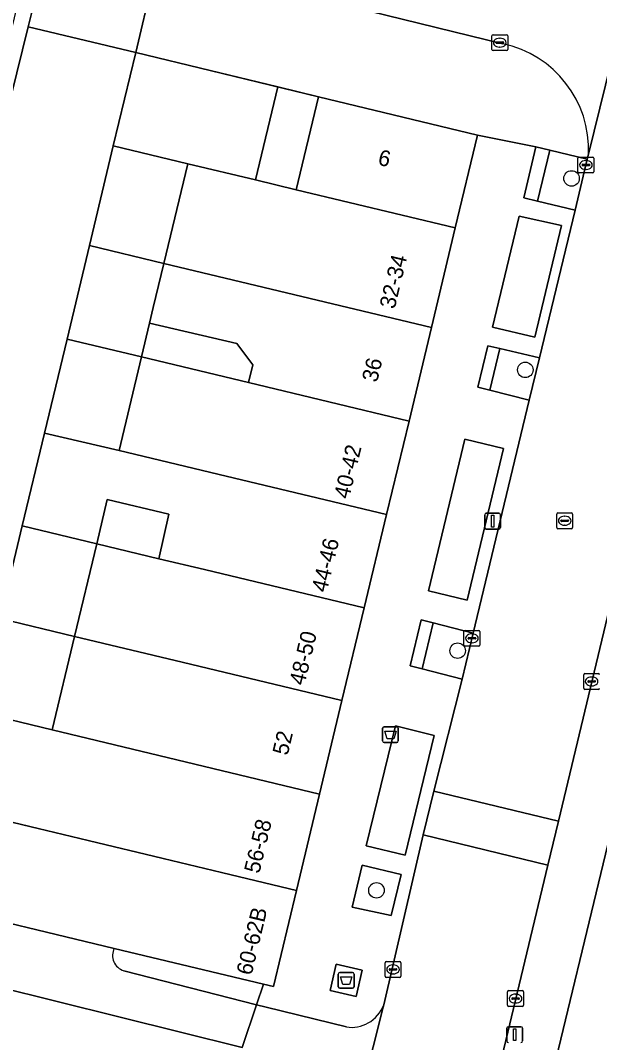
# Model space of a CAD drawing. Extents: x 162803 to 163818, y 381639 to 382475.
# Drawn here: x 163131.9 to 163168.5, y 382070.7 to 382135.2 of the extents above; entities that cross this region are included whole.
import ezdxf

# ---------------------------------------------------------------- set-up
doc = ezdxf.new("R2010")
doc.units = 0
for name, color, linetype in [('IMGEO_Afval_apart_plaats', 7, 'Continuous'), ('IMGEO_Afvalbak', 7, 'Continuous'), ('IMGEO_Boom', 7, 'Continuous'), ('IMGEO_Erf', 7, 'Continuous'), ('IMGEO_Groenvoorziening', 7, 'Continuous'), ('IMGEO_Kolk', 7, 'Continuous'), ('IMGEO_Lichtmast', 7, 'Continuous'), ('IMGEO_Muur', 7, 'Continuous'), ('IMGEO_Pand', 7, 'Continuous'), ('IMGEO_Pand_nummerreeks', 7, 'Continuous'), ('IMGEO_Rijbaan_lokaal_open', 7, 'Continuous'), ('IMGEO_Rioolput', 7, 'Continuous'), ('IMGEO_Voetpad_gesloten', 7, 'Continuous'), ('IMGEO_Voetpad_open', 7, 'Continuous')]:
    doc.layers.add(name, color=color, linetype=linetype)

msp = doc.modelspace()

# ---------------------------------------------------------------- linework, layer by layer
at = {"layer": 'IMGEO_Afval_apart_plaats'}
for p, q in [((163152.072, 382075.169), (163152.862, 382075.169)), ((163152.862, 382075.169), (163152.072, 382075.169)), ((163151.972, 382074.269), (163151.972, 382075.069)), ((163151.972, 382075.069), (163151.972, 382074.269)), ((163152.962, 382075.069), (163152.962, 382074.269)), ((163152.962, 382074.269), (163152.962, 382075.069)), ((163152.862, 382074.169), (163152.072, 382074.169)), ((163152.072, 382074.169), (163152.862, 382074.169))]:
    msp.add_line(p, q, dxfattribs=at)
msp.add_lwpolyline([(163152.115, 382074.883), (163152.819, 382074.883), (163152.67, 382074.413), (163152.264, 382074.413), (163152.115, 382074.883)], dxfattribs=at)
for centre, start, end in [((163152.072, 382075.069), 90, 180), ((163152.072, 382075.069), 90, 180), ((163152.862, 382075.069), 0, 90), ((163152.862, 382075.069), 360, 90), ((163152.072, 382074.269), 180, 270), ((163152.072, 382074.269), 180, 270), ((163152.862, 382074.269), 270, 0), ((163152.862, 382074.269), 270, 0)]:
    msp.add_arc(centre, 0.1, start, end, dxfattribs=at)
at = {"layer": 'IMGEO_Afvalbak'}
for p, q in [((163154.766, 382089.765), (163154.766, 382090.565)), ((163154.766, 382090.565), (163154.766, 382089.765)), ((163154.866, 382090.665), (163155.656, 382090.665)), ((163155.656, 382090.665), (163154.866, 382090.665)), ((163155.756, 382090.565), (163155.756, 382089.765)), ((163155.756, 382089.765), (163155.756, 382090.565)), ((163155.656, 382089.665), (163154.866, 382089.665)), ((163154.866, 382089.665), (163155.656, 382089.665))]:
    msp.add_line(p, q, dxfattribs=at)
msp.add_lwpolyline([(163154.909, 382090.379), (163155.613, 382090.379), (163155.464, 382089.909), (163155.058, 382089.909), (163154.909, 382090.379)], dxfattribs=at)
for centre, start, end in [((163154.866, 382090.565), 90, 180), ((163154.866, 382090.565), 90, 180), ((163155.656, 382090.565), 0, 90), ((163155.656, 382090.565), 360, 90), ((163154.866, 382089.765), 180, 270), ((163154.866, 382089.765), 180, 270), ((163155.656, 382089.765), 270, 0), ((163155.656, 382089.765), 270, 0)]:
    msp.add_arc(centre, 0.1, start, end, dxfattribs=at)
at = {"layer": 'IMGEO_Boom'}
for centre in [(163166.685, 382125.242), (163163.764, 382113.167), (163159.496, 382095.459), (163154.377, 382080.346)]:
    msp.add_circle(centre, 0.489, dxfattribs=at)
at = {"layer": 'IMGEO_Erf'}
for points in [[(163150.712, 382130.38), (163148.153, 382131.01), (163146.745, 382125.143), (163149.309, 382124.528)], [(163140.068, 382116.12), (163139.557, 382113.988), (163146.315, 382112.368), (163146.585, 382113.495), (163145.565, 382114.835)], [(163140.645, 382101.262), (163141.29, 382104.066), (163137.402, 382104.998), (163136.731, 382102.201)]]:
    msp.add_lwpolyline(points, close=True, dxfattribs=at)
msp.add_lwpolyline([(163172.549, 382098.026), (163172.362, 382097.253), (163161.731, 382053.278), (163161.928, 382051.741)], dxfattribs=at)
at = {"layer": 'IMGEO_Groenvoorziening'}
for points in [[(163127.256, 382138.666), (163127.019, 382137.696), (163131.809, 382136.528), (163128.65, 382123.499), (163129.559, 382123.281), (163132.413, 382134.805), (163133.023, 382137.267)], [(163165.305, 382127.024), (163164.439, 382127.233), (163163.664, 382124.026), (163164.529, 382123.814)], [(163167.679, 382126.45), (163165.305, 382127.024), (163164.529, 382123.814), (163166.904, 382123.234)], [(163166.054, 382122.27), (163163.382, 382122.859), (163161.691, 382115.861), (163164.358, 382115.23)], [(163162.162, 382114.515), (163161.409, 382114.694), (163160.774, 382112.07), (163161.525, 382111.883)], [(163164.661, 382113.922), (163162.162, 382114.515), (163161.525, 382111.883), (163164.02, 382111.263)], [(163162.391, 382108.22), (163159.962, 382108.804), (163157.656, 382099.238), (163160.104, 382098.647)], [(163157.962, 382097.218), (163157.206, 382097.414), (163156.496, 382094.5), (163157.253, 382094.308)], [(163160.479, 382096.566), (163157.962, 382097.218), (163157.253, 382094.308), (163159.78, 382093.666)], [(163158.023, 382090.12), (163155.573, 382090.71), (163153.732, 382083.151), (163156.18, 382082.555)], [(163155.298, 382078.76), (163155.927, 382081.355), (163153.466, 382081.935), (163152.837, 382079.286)]]:
    msp.add_lwpolyline(points, close=True, dxfattribs=at)
at = {"layer": 'IMGEO_Kolk'}
for p, q in [((163161.658, 382133.378), (163161.658, 382134.23)), ((163161.733, 382134.304), (163162.585, 382134.304)), ((163161.917, 382133.798), (163161.917, 382133.81)), ((163162.355, 382133.761), (163161.957, 382133.761)), ((163161.96, 382133.847), (163162.358, 382133.847)), ((163162.146, 382134.084), (163162.171, 382134.084)), ((163162.401, 382133.81), (163162.401, 382133.798)), ((163162.659, 382134.23), (163162.659, 382133.378)), ((163162.585, 382133.304), (163161.733, 382133.304)), ((163162.169, 382133.524), (163162.144, 382133.524)), ((163167.089, 382125.662), (163167.089, 382126.514)), ((163167.164, 382126.588), (163168.016, 382126.588)), ((163167.348, 382126.082), (163167.348, 382126.094)), ((163167.786, 382126.045), (163167.388, 382126.045)), ((163167.391, 382126.131), (163167.789, 382126.131)), ((163167.577, 382126.368), (163167.602, 382126.368)), ((163167.832, 382126.094), (163167.832, 382126.082)), ((163168.09, 382126.514), (163168.09, 382125.662)), ((163168.016, 382125.588), (163167.164, 382125.588)), ((163167.6, 382125.808), (163167.575, 382125.808)), ((163159.899, 382095.816), (163159.899, 382096.668)), ((163159.974, 382096.742), (163160.826, 382096.742)), ((163160.387, 382096.522), (163160.412, 382096.522)), ((163160.9, 382096.668), (163160.9, 382095.816)), ((163160.826, 382095.742), (163159.974, 382095.742)), ((163160.158, 382096.236), (163160.158, 382096.248)), ((163160.596, 382096.199), (163160.198, 382096.199)), ((163160.201, 382096.285), (163160.599, 382096.285)), ((163160.41, 382095.962), (163160.385, 382095.962)), ((163160.642, 382096.248), (163160.642, 382096.236)), ((163167.449, 382093.094), (163167.449, 382093.946)), ((163167.524, 382094.02), (163168.376, 382094.02)), ((163167.937, 382093.8), (163167.962, 382093.8)), ((163167.708, 382093.514), (163167.708, 382093.526)), ((163168.146, 382093.477), (163167.748, 382093.477)), ((163167.751, 382093.563), (163168.149, 382093.563)), ((163167.96, 382093.24), (163167.935, 382093.24)), ((163168.192, 382093.526), (163168.192, 382093.514)), ((163168.376, 382093.02), (163167.524, 382093.02)), ((163154.923, 382074.932), (163154.923, 382075.784)), ((163154.998, 382075.858), (163155.85, 382075.858)), ((163155.924, 382075.784), (163155.924, 382074.932)), ((163155.182, 382075.352), (163155.182, 382075.364)), ((163155.62, 382075.315), (163155.222, 382075.315)), ((163155.225, 382075.401), (163155.623, 382075.401)), ((163155.434, 382075.078), (163155.409, 382075.078)), ((163155.411, 382075.638), (163155.436, 382075.638)), ((163155.666, 382075.364), (163155.666, 382075.352)), ((163155.85, 382074.858), (163154.998, 382074.858)), ((163162.65, 382073.095), (163162.65, 382073.947)), ((163162.725, 382074.021), (163163.577, 382074.021)), ((163163.138, 382073.801), (163163.163, 382073.801)), ((163163.651, 382073.947), (163163.651, 382073.095)), ((163162.909, 382073.515), (163162.909, 382073.527)), ((163163.347, 382073.478), (163162.949, 382073.478)), ((163162.952, 382073.564), (163163.35, 382073.564)), ((163163.161, 382073.241), (163163.136, 382073.241)), ((163163.393, 382073.527), (163163.393, 382073.515)), ((163163.577, 382073.021), (163162.725, 382073.021))]:
    msp.add_line(p, q, dxfattribs=at)
for points in [[(163161.658, 382133.378), (163161.658, 382134.23)], [(163161.733, 382134.304), (163162.585, 382134.304)], [(163162.659, 382134.23), (163162.659, 382133.378)], [(163162.585, 382133.304), (163161.733, 382133.304)], [(163167.089, 382125.662), (163167.089, 382126.514)], [(163167.164, 382126.588), (163168.016, 382126.588)], [(163168.09, 382126.514), (163168.09, 382125.662)], [(163168.016, 382125.588), (163167.164, 382125.588)], [(163159.899, 382095.816), (163159.899, 382096.668)], [(163159.974, 382096.742), (163160.826, 382096.742)], [(163160.9, 382096.668), (163160.9, 382095.816)], [(163160.826, 382095.742), (163159.974, 382095.742)], [(163167.449, 382093.094), (163167.449, 382093.946)], [(163167.524, 382094.02), (163168.376, 382094.02)], [(163168.376, 382093.02), (163167.524, 382093.02)], [(163154.923, 382074.932), (163154.923, 382075.784)], [(163154.998, 382075.858), (163155.85, 382075.858)], [(163155.924, 382075.784), (163155.924, 382074.932)], [(163155.85, 382074.858), (163154.998, 382074.858)], [(163162.65, 382073.095), (163162.65, 382073.947)], [(163162.725, 382074.021), (163163.577, 382074.021)], [(163163.651, 382073.947), (163163.651, 382073.095)], [(163163.577, 382073.021), (163162.725, 382073.021)]]:
    msp.add_lwpolyline(points, dxfattribs=at)
for centre, radius, start, end in [((163161.735, 382134.228), 0.0765, 91.55205, 178.44795), ((163161.735, 382134.228), 0.0765, 91.55205, 178.44795), ((163161.957, 382133.807), 0.0403, 85.87752, 175.75265), ((163161.954, 382133.797), 0.0366, 178.93798, 274.71019), ((163162.358, 382133.804), 0.043, 264.86636, 352.45326), ((163162.362, 382133.809), 0.0386, 1.73085, 96.63898), ((163162.583, 382134.228), 0.0765, 1.55205, 88.44795), ((163162.583, 382134.228), 0.0765, 1.55205, 88.44795), ((163161.735, 382133.38), 0.0765, 181.55205, 268.44795), ((163161.735, 382133.38), 0.0765, 181.55205, 268.44795), ((163162.583, 382133.38), 0.0765, 271.55205, 358.44795), ((163162.583, 382133.38), 0.0765, 271.55205, 358.44795), ((163167.166, 382126.512), 0.0765, 91.55205, 178.44795), ((163167.166, 382126.512), 0.0765, 91.55205, 178.44795), ((163167.388, 382126.091), 0.0403, 85.87752, 175.75265), ((163167.385, 382126.081), 0.0366, 178.93798, 274.71019), ((163167.789, 382126.088), 0.043, 264.86636, 352.45326), ((163167.793, 382126.093), 0.0386, 1.73085, 96.63898), ((163168.014, 382126.512), 0.0765, 1.55205, 88.44795), ((163168.014, 382126.512), 0.0765, 1.55205, 88.44795), ((163167.166, 382125.664), 0.0765, 181.55205, 268.44795), ((163167.166, 382125.664), 0.0765, 181.55205, 268.44795), ((163168.014, 382125.664), 0.0765, 271.55205, 358.44795), ((163168.014, 382125.664), 0.0765, 271.55205, 358.44795), ((163159.976, 382096.666), 0.0765, 91.55205, 178.44795), ((163159.976, 382096.666), 0.0765, 91.55205, 178.44795), ((163160.824, 382096.666), 0.0765, 1.55205, 88.44795), ((163160.824, 382096.666), 0.0765, 1.55205, 88.44795), ((163159.976, 382095.818), 0.0765, 181.55205, 268.44795), ((163159.976, 382095.818), 0.0765, 181.55205, 268.44795), ((163160.198, 382096.245), 0.0403, 85.87752, 175.75265), ((163160.195, 382096.235), 0.0366, 178.93798, 274.71019), ((163160.599, 382096.242), 0.043, 264.86636, 352.45326), ((163160.603, 382096.247), 0.0386, 1.73085, 96.63898), ((163160.824, 382095.818), 0.0765, 271.55205, 358.44795), ((163160.824, 382095.818), 0.0765, 271.55205, 358.44795), ((163167.526, 382093.944), 0.0765, 91.55205, 178.44795), ((163167.526, 382093.944), 0.0765, 91.55205, 178.44795), ((163168.374, 382093.944), 0.0765, 1.55205, 88.44795), ((163168.374, 382093.944), 0.0765, 1.55205, 88.44795), ((163167.748, 382093.523), 0.0403, 85.87752, 175.75265), ((163167.745, 382093.513), 0.0366, 178.93798, 274.71019), ((163168.149, 382093.52), 0.043, 264.86636, 352.45326), ((163168.153, 382093.525), 0.0386, 1.73085, 96.63898), ((163167.526, 382093.096), 0.0765, 181.55205, 268.44795), ((163167.526, 382093.096), 0.0765, 181.55205, 268.44795), ((163168.374, 382093.096), 0.0765, 271.55205, 358.44795), ((163168.374, 382093.096), 0.0765, 271.55205, 358.44795), ((163155, 382075.782), 0.0765, 91.55205, 178.44795), ((163155, 382075.782), 0.0765, 91.55205, 178.44795), ((163155.848, 382075.782), 0.0765, 1.55205, 88.44795), ((163155.848, 382075.782), 0.0765, 1.55205, 88.44795), ((163155.222, 382075.361), 0.0403, 85.87752, 175.75265), ((163155.219, 382075.351), 0.0366, 178.93798, 274.71019), ((163155.623, 382075.358), 0.043, 264.86636, 352.45326), ((163155.627, 382075.363), 0.0386, 1.73085, 96.63898), ((163155, 382074.934), 0.0765, 181.55205, 268.44795), ((163155, 382074.934), 0.0765, 181.55205, 268.44795), ((163155.848, 382074.934), 0.0765, 271.55205, 358.44795), ((163155.848, 382074.934), 0.0765, 271.55205, 358.44795), ((163162.727, 382073.945), 0.0765, 91.55205, 178.44795), ((163162.727, 382073.945), 0.0765, 91.55205, 178.44795), ((163163.575, 382073.945), 0.0765, 1.55205, 88.44795), ((163163.575, 382073.945), 0.0765, 1.55205, 88.44795), ((163162.949, 382073.524), 0.0403, 85.87752, 175.75265), ((163162.946, 382073.514), 0.0366, 178.93798, 274.71019), ((163163.35, 382073.521), 0.043, 264.86636, 352.45326), ((163163.354, 382073.526), 0.0386, 1.73085, 96.63898), ((163162.727, 382073.097), 0.0765, 181.55205, 268.44795), ((163162.727, 382073.097), 0.0765, 181.55205, 268.44795), ((163163.575, 382073.097), 0.0765, 271.55205, 358.44795), ((163163.575, 382073.097), 0.0765, 271.55205, 358.44795)]:
    msp.add_arc(centre, radius, start, end, dxfattribs=at)
for centre, major_axis, ratio, start_param, end_param in [((163162.145, 382133.804), (-0.387, 0.002), 0.722429, 4.712389, 7.853982), ((163162.17, 382133.804), (-0.39, 0.002), 0.717154, 1.570796, 4.712389), ((163167.576, 382126.088), (-0.387, 0.002), 0.722429, 4.712389, 7.853982), ((163167.601, 382126.088), (-0.39, 0.002), 0.717154, 1.570796, 4.712389), ((163160.386, 382096.242), (-0.387, 0.002), 0.722429, 4.712389, 7.853982), ((163160.411, 382096.242), (-0.39, 0.002), 0.717154, 1.570796, 4.712389), ((163167.936, 382093.52), (-0.387, 0.002), 0.722429, 4.712389, 7.853982), ((163167.961, 382093.52), (-0.39, 0.002), 0.717154, 1.570796, 4.712389), ((163155.41, 382075.358), (-0.387, 0.002), 0.722429, 4.712389, 7.853982), ((163155.435, 382075.358), (-0.39, 0.002), 0.717154, 1.570796, 4.712389), ((163163.137, 382073.521), (-0.387, 0.002), 0.722429, 4.712389, 7.853982), ((163163.162, 382073.521), (-0.39, 0.002), 0.717154, 1.570796, 4.712389)]:
    msp.add_ellipse(centre, major_axis=major_axis, ratio=ratio, start_param=start_param, end_param=end_param, dxfattribs=at)
at = {"layer": 'IMGEO_Lichtmast'}
for p, q in [((163161.304, 382104.133), (163162.094, 382104.133)), ((163162.094, 382104.133), (163161.304, 382104.133)), ((163161.204, 382103.233), (163161.204, 382104.033)), ((163161.204, 382104.033), (163161.204, 382103.233)), ((163162.194, 382104.033), (163162.194, 382103.233)), ((163162.194, 382103.233), (163162.194, 382104.033)), ((163162.094, 382103.133), (163161.304, 382103.133)), ((163161.304, 382103.133), (163162.094, 382103.133)), ((163162.6, 382070.846), (163162.6, 382071.646)), ((163162.6, 382071.646), (163162.6, 382070.846)), ((163162.7, 382071.746), (163163.49, 382071.746)), ((163163.49, 382071.746), (163162.7, 382071.746)), ((163163.59, 382071.646), (163163.59, 382070.846)), ((163163.59, 382070.846), (163163.59, 382071.646))]:
    msp.add_line(p, q, dxfattribs=at)
for points in [[(163161.624, 382104.008), (163161.774, 382104.008), (163161.774, 382103.258), (163161.624, 382103.258), (163161.624, 382104.008)], [(163163.02, 382071.621), (163163.17, 382071.621), (163163.17, 382070.871), (163163.02, 382070.871), (163163.02, 382071.621)]]:
    msp.add_lwpolyline(points, dxfattribs=at)
for centre, start, end in [((163161.304, 382104.033), 90, 180), ((163161.304, 382104.033), 90, 180), ((163162.094, 382104.033), 0, 90), ((163162.094, 382104.033), 360, 90), ((163161.304, 382103.233), 180, 270), ((163161.304, 382103.233), 180, 270), ((163162.094, 382103.233), 270, 0), ((163162.094, 382103.233), 270, 0), ((163162.7, 382071.646), 90, 180), ((163162.7, 382071.646), 90, 180), ((163163.49, 382071.646), 0, 90), ((163163.49, 382071.646), 360, 90), ((163162.7, 382070.846), 180, 270), ((163162.7, 382070.846), 180, 270), ((163163.49, 382070.846), 270, 0), ((163163.49, 382070.846), 270, 0)]:
    msp.add_arc(centre, 0.1, start, end, dxfattribs=at)
at = {"layer": 'IMGEO_Muur'}
for points in [[(163143.891, 382132.058), (163150.712, 382130.38)], [(163161.731, 382053.278), (163172.362, 382097.253)]]:
    msp.add_lwpolyline(points, dxfattribs=at)
at = {"layer": 'IMGEO_Pand'}
for points in [[(163148.153, 382131.01), (163143.891, 382132.058), (163139.19, 382133.185), (163137.778, 382127.293), (163142.478, 382126.166), (163146.745, 382125.143)], [(163149.309, 382124.528), (163159.352, 382122.119), (163160.755, 382127.971), (163150.712, 382130.38)], [(163140.972, 382119.886), (163142.478, 382126.166), (163137.778, 382127.293), (163136.272, 382121.013)], [(163159.352, 382122.119), (163149.309, 382124.528), (163146.745, 382125.143), (163142.478, 382126.166), (163140.972, 382119.886), (163147.729, 382118.264), (163157.846, 382115.839)], [(163140.972, 382119.886), (163136.272, 382121.013), (163134.859, 382115.115), (163139.557, 382113.988), (163140.068, 382116.12), (163140.302, 382117.095)], [(163157.846, 382115.839), (163147.729, 382118.264), (163140.972, 382119.886), (163140.302, 382117.095), (163140.068, 382116.12), (163145.565, 382114.835), (163146.585, 382113.495), (163146.315, 382112.368), (163156.431, 382109.942)], [(163133.436, 382109.18), (163138.139, 382108.074), (163139.557, 382113.988), (163134.859, 382115.115)], [(163156.431, 382109.942), (163146.315, 382112.368), (163139.557, 382113.988), (163138.139, 382108.074), (163144.896, 382106.455), (163155.018, 382104.048)], [(163140.645, 382101.262), (163143.521, 382100.573), (163153.605, 382098.155), (163155.018, 382104.048), (163144.896, 382106.455), (163138.139, 382108.074), (163133.436, 382109.18), (163132.033, 382103.327), (163136.731, 382102.201), (163137.402, 382104.998), (163141.29, 382104.066)], [(163130.633, 382097.486), (163135.33, 382096.359), (163136.731, 382102.201), (163132.033, 382103.327)], [(163136.731, 382102.201), (163135.33, 382096.359), (163142.12, 382094.731), (163152.204, 382092.313), (163153.605, 382098.155), (163143.521, 382100.573), (163140.645, 382101.262)], [(163130.633, 382097.486), (163129.221, 382091.594), (163133.917, 382090.468), (163135.33, 382096.359)], [(163135.33, 382096.359), (163133.917, 382090.468), (163150.791, 382086.421), (163152.204, 382092.313), (163142.12, 382094.731)], [(163127.761, 382085.503), (163149.33, 382080.33), (163150.791, 382086.421), (163133.917, 382090.468), (163129.221, 382091.594)], [(163149.33, 382080.33), (163127.761, 382085.503), (163126.31, 382079.45), (163137.842, 382076.687), (163147.251, 382074.43), (163147.253, 382074.43), (163147.879, 382074.28)]]:
    msp.add_lwpolyline(points, close=True, dxfattribs=at)
at = {"layer": 'IMGEO_Rijbaan_lokaal_open'}
for points in [[(163172.306, 382111.79), (163181.993, 382151.527), (163174.142, 382153.38), (163171.317, 382141.304), (163167.754, 382126.763), (163167.679, 382126.45), (163166.904, 382123.234), (163164.661, 382113.922), (163164.02, 382111.263), (163160.479, 382096.566), (163159.78, 382093.666), (163158.005, 382086.598), (163165.855, 382084.706), (163169.308, 382099.118)], [(163167.754, 382126.763), (163171.317, 382141.304)], [(163133.375, 382138.855), (163133.023, 382137.267), (163132.413, 382134.805), (163139.19, 382133.185), (163140.227, 382137.573)], [(163142.353, 382138.657), (163162.346, 382133.731)], [(163134.859, 382115.115), (163136.272, 382121.013), (163137.778, 382127.293), (163139.19, 382133.185), (163132.413, 382134.805), (163129.559, 382123.281), (163129.714, 382123.244), (163130.175, 382123.133), (163120.073, 382080.932), (163119.585, 382081.072), (163118.665, 382077.202), (163145.899, 382070.444), (163146.816, 382073.136), (163138.433, 382075.277)], [(163137.842, 382076.687), (163126.31, 382079.45), (163127.761, 382085.503), (163129.221, 382091.594), (163130.633, 382097.486), (163132.033, 382103.327), (163133.436, 382109.18), (163134.859, 382115.115)], [(163152.479, 382071.728), (163147.417, 382072.983), (163146.816, 382073.136), (163145.899, 382070.444), (163118.665, 382077.202), (163119.585, 382081.072), (163101.444, 382085.414)], [(163157.77, 382051.207), (163158.197, 382052.792), (163165.19, 382081.932), (163157.326, 382083.853), (163154.833, 382073.132), (163154.796, 382072.986), (163152.284, 382062.975)], [(163152.284, 382062.975), (163154.796, 382072.986), (163154.833, 382073.132)]]:
    msp.add_lwpolyline(points, dxfattribs=at)
msp.add_lwpolyline([(163165.855, 382084.706), (163158.005, 382086.598), (163157.326, 382083.853), (163165.19, 382081.932)], close=True, dxfattribs=at)
for centre, radius, start, end in [((163160.934, 382127.052), 6.826, 357.56968, 78.06179), ((163138.73, 382076.23), 0.998, 152.76243, 252.71946), ((163152.865, 382073.811), 2.082, 298.45364, 340.95325), ((163152.794, 382073.893), 2.188, 261.73205, 299.07516)]:
    msp.add_arc(centre, radius, start, end, dxfattribs=at)
at = {"layer": 'IMGEO_Rioolput'}
for p, q in [((163165.752, 382103.227), (163165.752, 382104.079)), ((163165.827, 382104.153), (163166.679, 382104.153)), ((163166.753, 382104.079), (163166.753, 382103.227)), ((163166.011, 382103.647), (163166.011, 382103.659)), ((163166.449, 382103.61), (163166.051, 382103.61)), ((163166.054, 382103.696), (163166.452, 382103.696)), ((163166.24, 382103.933), (163166.265, 382103.933)), ((163166.495, 382103.659), (163166.495, 382103.647)), ((163166.679, 382103.153), (163165.827, 382103.153)), ((163166.263, 382103.373), (163166.238, 382103.373))]:
    msp.add_line(p, q, dxfattribs=at)
for points in [[(163165.752, 382103.227), (163165.752, 382104.079)], [(163165.827, 382104.153), (163166.679, 382104.153)], [(163166.753, 382104.079), (163166.753, 382103.227)], [(163166.679, 382103.153), (163165.827, 382103.153)]]:
    msp.add_lwpolyline(points, dxfattribs=at)
for centre, radius, start, end in [((163165.829, 382104.077), 0.0765, 91.55205, 178.44795), ((163165.829, 382104.077), 0.0765, 91.55205, 178.44795), ((163166.677, 382104.077), 0.0765, 1.55205, 88.44795), ((163166.677, 382104.077), 0.0765, 1.55205, 88.44795), ((163166.051, 382103.656), 0.0403, 85.87752, 175.75265), ((163166.048, 382103.646), 0.0366, 178.93798, 274.71019), ((163166.452, 382103.653), 0.043, 264.86636, 352.45326), ((163166.456, 382103.658), 0.0386, 1.73085, 96.63898), ((163165.829, 382103.229), 0.0765, 181.55205, 268.44795), ((163165.829, 382103.229), 0.0765, 181.55205, 268.44795), ((163166.677, 382103.229), 0.0765, 271.55205, 358.44795), ((163166.677, 382103.229), 0.0765, 271.55205, 358.44795)]:
    msp.add_arc(centre, radius, start, end, dxfattribs=at)
for centre, major_axis, ratio, start_param, end_param in [((163166.239, 382103.653), (-0.387, 0.002), 0.722429, 4.712389, 7.853982), ((163166.264, 382103.653), (-0.39, 0.002), 0.717154, 1.570796, 4.712389)]:
    msp.add_ellipse(centre, major_axis=major_axis, ratio=ratio, start_param=start_param, end_param=end_param, dxfattribs=at)
at = {"layer": 'IMGEO_Voetpad_gesloten'}
msp.add_lwpolyline([(163153.483, 382075.306), (163151.84, 382075.691), (163151.451, 382074.033), (163153.094, 382073.648)], close=True, dxfattribs=at)
at = {"layer": 'IMGEO_Voetpad_open'}
for points in [[(163162.346, 382133.731), (163142.353, 382138.657)], [(163140.227, 382137.573), (163139.19, 382133.185), (163143.891, 382132.058), (163148.153, 382131.01), (163150.712, 382130.38), (163160.755, 382127.971), (163164.439, 382127.233), (163165.305, 382127.024), (163167.679, 382126.45), (163167.754, 382126.763)], [(163164.02, 382111.263), (163161.525, 382111.883), (163160.774, 382112.07), (163161.409, 382114.694), (163162.162, 382114.515), (163164.661, 382113.922), (163166.904, 382123.234), (163164.529, 382123.814), (163163.664, 382124.026), (163164.439, 382127.233), (163160.755, 382127.971), (163159.352, 382122.119), (163157.846, 382115.839), (163156.431, 382109.942), (163155.018, 382104.048), (163153.605, 382098.155), (163152.204, 382092.313), (163150.791, 382086.421), (163149.33, 382080.33), (163147.879, 382074.28), (163147.253, 382074.43), (163147.251, 382074.43), (163146.816, 382073.136), (163147.417, 382072.983), (163152.479, 382071.728)], [(163154.833, 382073.132), (163157.326, 382083.853), (163158.005, 382086.598), (163159.78, 382093.666), (163157.253, 382094.308), (163156.496, 382094.5), (163157.206, 382097.414), (163157.962, 382097.218), (163160.479, 382096.566), (163164.02, 382111.263)], [(163169.308, 382099.118), (163165.855, 382084.706), (163165.19, 382081.932), (163158.197, 382052.792), (163157.77, 382051.207)], [(163159.769, 382045.519), (163161.731, 382053.278), (163172.362, 382097.253)], [(163138.433, 382075.277), (163146.816, 382073.136), (163147.251, 382074.43), (163137.842, 382076.687)]]:
    msp.add_lwpolyline(points, dxfattribs=at)
for points in [[(163161.691, 382115.861), (163163.382, 382122.859), (163166.054, 382122.27), (163164.358, 382115.23)], [(163159.962, 382108.804), (163162.391, 382108.22), (163160.104, 382098.647), (163157.656, 382099.238)], [(163158.023, 382090.12), (163156.18, 382082.555), (163153.732, 382083.151), (163155.573, 382090.71)], [(163155.927, 382081.355), (163155.298, 382078.76), (163152.837, 382079.286), (163153.466, 382081.935)], [(163153.483, 382075.306), (163153.094, 382073.648), (163151.451, 382074.033), (163151.84, 382075.691)]]:
    msp.add_lwpolyline(points, close=True, dxfattribs=at)
for centre, radius, start, end in [((163160.934, 382127.052), 6.826, 357.56968, 78.06179), ((163138.73, 382076.23), 0.998, 152.76243, 252.71946), ((163152.865, 382073.811), 2.082, 298.45364, 340.95325), ((163152.794, 382073.893), 2.188, 261.73205, 299.07516)]:
    msp.add_arc(centre, radius, start, end, dxfattribs=at)

# ---------------------------------------------------------------- texts
at = {"layer": 'IMGEO_Pand_nummerreeks'}
for s, rotation, p in [('6', 346.51139, (163154.414, 382126.119)), ('32-34', 76.51278, (163155.524, 382116.964)), ('36', 76.50705, (163154.415, 382112.338)), ('40-42', 76.51851, (163152.649, 382104.977)), ('44-46', 76.5164, (163151.236, 382099.087)), ('48-50', 76.51428, (163149.83, 382093.222)), ('52', 76.5142, (163148.772, 382088.811)), ('56-58', 76.51174, (163146.986, 382081.364)), ('60-62B', 76.51278, (163146.495, 382074.942))]:
    msp.add_text(s, height=1, rotation=rotation, dxfattribs=at).set_placement(p)

doc.saveas('drawing.dxf')
